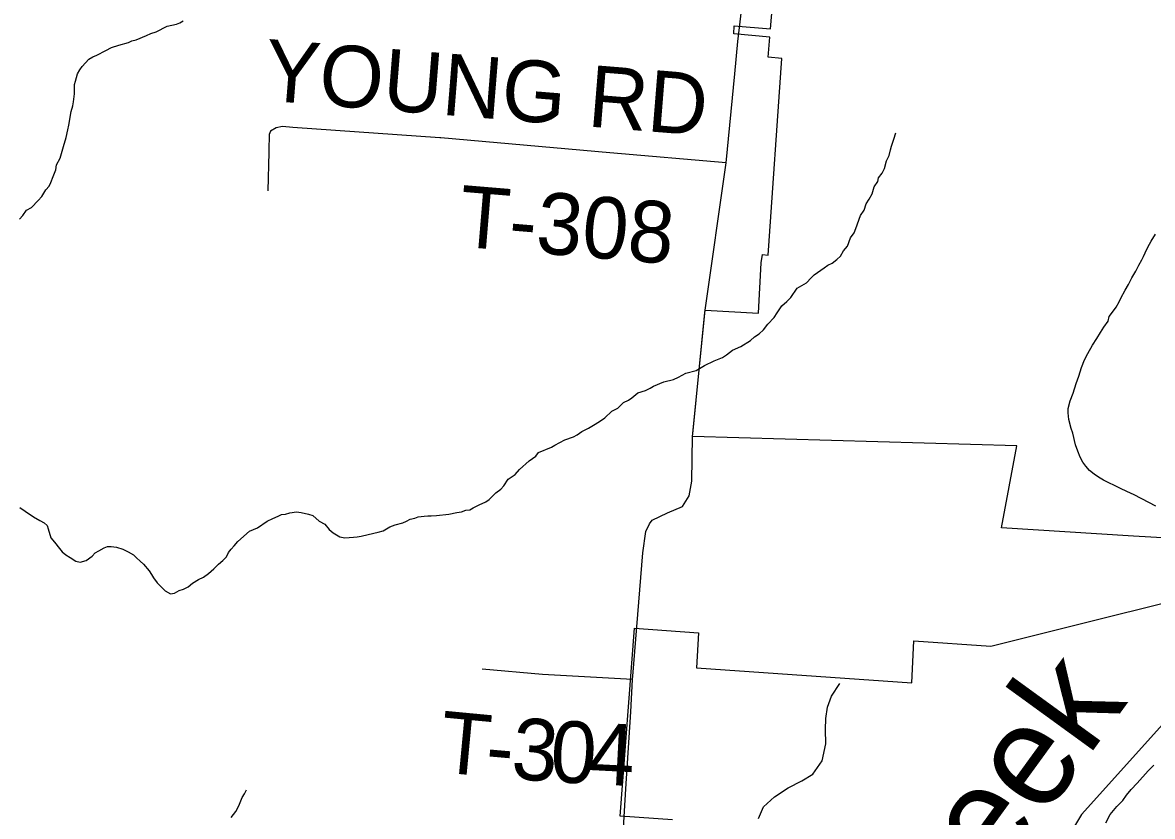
# Model space of a CAD drawing. Extents: x 1310247 to 1664935, y 235267 to 584339.
# Drawn here: x 1473756 to 1479257, y 371649 to 375516 of the extents above; entities that cross this region are included whole.
import ezdxf

# ---------------------------------------------------------------- set-up
doc = ezdxf.new("R2010")
doc.units = 0
for name, color, linetype in [('GM_X_Corporation', 7, 'Continuous'), ('GM_X_Minor_River', 7, 'Continuous'), ('GM_X_Minor_River_Text', 7, 'Continuous'), ('GM_X_Township_Road', 7, 'Continuous'), ('GM_X_Township_Road_Text', 7, 'Continuous')]:
    doc.layers.add(name, color=color, linetype=linetype)

msp = doc.modelspace()

# ---------------------------------------------------------------- linework, layer by layer
at = {"layer": 'GM_X_Corporation'}
for points in [[(1479868, 372973.8), (1479166.1, 373013.9), (1478522.1, 373055.4), (1478596.8, 373453.6), (1477017.5, 373499.2), (1477079.4, 374115.1), (1477339.6, 374100.8), (1477352.5, 374346.2), (1477358.1, 374385.8), (1477386, 374383.3), (1477452.9, 375341.3), (1477386.2, 375347.1), (1477389, 375387), (1477394.1, 375445.4), (1477218.6, 375460.8), (1477221.4, 375500.7), (1477397.6, 375485.3), (1477424.2, 375789.9)], [(1476920.4, 371632.2), (1476666, 371650), (1476735.4, 372566.2), (1477046.7, 372543.4), (1477037.8, 372373.6), (1478085.2, 372300.4), (1478096, 372505.2), (1478471, 372478.9), (1479816.8, 372814.6)], [(1479425.4, 372228.2), (1478912.8, 371658.8), (1478766, 371414.4)]]:
    msp.add_lwpolyline(points, dxfattribs=at)
at = {"layer": 'GM_X_Minor_River'}
for points in [[(1473740.6, 374558.2), (1473757, 374576), (1473775.5, 374601.8), (1473799.8, 374615.4), (1473832.5, 374649), (1473848.9, 374668.8), (1473869.5, 374700.6), (1473885.9, 374718.3), (1473894.2, 374736.3), (1473904.7, 374766.2), (1473917.3, 374798.1), (1473921.7, 374822.2), (1473938.4, 374856), (1473955.4, 374912), (1473968.2, 374955.9), (1473976.8, 374993.9), (1473981.2, 375016), (1473992.4, 375082), (1474000.9, 375110), (1474003.2, 375130.1), (1474007.9, 375168.1), (1474008.6, 375214.3), (1474012.9, 375230.3), (1474023.6, 375266.3), (1474034, 375286.2), (1474046.3, 375302), (1474079, 375337.6), (1474097.2, 375349.4), (1474117.4, 375357), (1474162, 375380.4), (1474188.3, 375394), (1474224.7, 375405.4), (1474271, 375418.6), (1474287.2, 375426.4), (1474309.4, 375432), (1474360, 375453.2), (1474380.2, 375462.9), (1474406.4, 375470.5), (1474459.1, 375497.7), (1474505.4, 375508.9), (1474521.6, 375514.7), (1474537.8, 375524.4)], [(1477036.4, 373821.6), (1477060.7, 373835.3), (1477076.9, 373845), (1477123.5, 373868.3), (1477163.9, 373883.7), (1477184.2, 373897.4), (1477212.7, 373921), (1477253.1, 373938.3), (1477299.8, 373967.7), (1477320.2, 373985.4), (1477342.5, 373999), (1477362.9, 374018.8), (1477385.4, 374046.5), (1477416.1, 374080.1), (1477430.5, 374102), (1477453.2, 374135.7), (1477477.6, 374157.4), (1477496, 374177.1), (1477526.9, 374222.8), (1477573.5, 374248.1), (1477596, 374271.8), (1477610.3, 374287.6), (1477659, 374320.9), (1477677.3, 374334.6), (1477697.6, 374344.3), (1477720, 374362), (1477738.3, 374377.8), (1477752.8, 374403.6), (1477773.2, 374427.4), (1477788, 374467.3), (1477804.4, 374491.1), (1477812.8, 374513), (1477836, 374576.9), (1477854.5, 374602.7), (1477863, 374632.7), (1477877.5, 374656.5), (1477892, 374682.4), (1477902.6, 374716.3), (1477921.1, 374742.1), (1477923.4, 374760.2), (1477941.8, 374781.9), (1477952.3, 374805.9), (1477962.9, 374841.8), (1477975.4, 374867.7), (1477981.9, 374895.7), (1477986.2, 374913.7), (1477998.8, 374947.6), (1478007.4, 374979.6)], [(1479273.5, 373159.8), (1479239.7, 373178.5), (1479168, 373215.9), (1479132.2, 373232.6), (1479102.3, 373247.2), (1479072.4, 373261.8), (1479044.6, 373274.3), (1479018.7, 373286.8), (1478994.8, 373301.3), (1478973, 373315.7), (1478951.2, 373334.2), (1478933.5, 373354.6), (1478917.8, 373374.9), (1478906.1, 373399.2), (1478894.6, 373427.6), (1478883.1, 373459.9), (1478870, 373516.4), (1478862.3, 373538.6), (1478851, 373583), (1478847.6, 373615.2), (1478847.9, 373635.3), (1478856.6, 373673.3), (1478871.2, 373711.2), (1478886.1, 373757.1), (1478898.7, 373793), (1478911.5, 373835), (1478926.2, 373872.9), (1478942.8, 373904.8), (1478965.5, 373944.5), (1478986.1, 373976.3), (1479004.7, 374006.1), (1479021.2, 374031.9), (1479041.8, 374061.7), (1479046.1, 374083.7), (1479058.5, 374099.6), (1479081, 374129.3), (1479095.5, 374155.2), (1479103.9, 374173.1), (1479124.6, 374212.9), (1479141.1, 374240.7), (1479157.7, 374272.6), (1479176.3, 374304.4), (1479190.9, 374334.3), (1479205.4, 374360.1), (1479213.7, 374376), (1479222, 374394), (1479234.5, 374421.9), (1479251.1, 374451.7), (1479271.7, 374485.5)], [(1474344.7, 372878.5), (1474372.2, 372845.9), (1474384, 372827.6), (1474393.7, 372811.4), (1474411.4, 372787), (1474429.1, 372768.5), (1474450.9, 372748.1), (1474476.7, 372733.6), (1474494.9, 372737.3), (1474519.1, 372748.9), (1474539.3, 372756.6), (1474561.6, 372768.2), (1474584, 372785.9), (1474612.4, 372803.5), (1474636.7, 372815.1), (1474661.1, 372832.8), (1474687.5, 372854.4), (1474710, 372878.1), (1474730.4, 372895.8), (1474748.7, 372913.6), (1474759.2, 372935.5), (1474771.5, 372951.4), (1474785.8, 372967.2), (1474804.2, 372989), (1474861.2, 373038.2), (1474899.7, 373055.6), (1474946.4, 373086.9), (1474974.7, 373100.5), (1475001, 373112.1), (1475017.2, 373119.8), (1475035.3, 373121.5), (1475057.5, 373127.1), (1475089.7, 373132.6), (1475111.7, 373130.2), (1475147.7, 373121.5), (1475169.7, 373115.1), (1475199.3, 373086.5), (1475227.2, 373072), (1475248.8, 373047.5), (1475268.6, 373031.1), (1475300.4, 373010.4), (1475324.4, 373006), (1475366.6, 373009.2), (1475384.7, 373011), (1475404.9, 373014.6), (1475439.1, 373022), (1475487.5, 373033.2), (1475511.7, 373040.9), (1475544.1, 373060.4), (1475570.4, 373070), (1475606.7, 373079.4), (1475624.9, 373087.1), (1475643.1, 373096.8), (1475665.3, 373102.5), (1475681.4, 373108.2), (1475711.6, 373111.7), (1475729.7, 373113.4), (1475745.7, 373113.1), (1475771.9, 373114.6), (1475832.2, 373121.6), (1475870.5, 373129), (1475892.6, 373132.6), (1475914.8, 373140.3), (1475932.9, 373142), (1475949.1, 373151.7), (1475979.5, 373167.2), (1476011.9, 373180.7), (1476028.1, 373192.5), (1476060.8, 373226.1), (1476085.2, 373243.7), (1476099.5, 373259.5), (1476120.1, 373291.3), (1476154.6, 373314.8), (1476175.1, 373338.6), (1476222, 373381.9), (1476254.5, 373403.5), (1476268.8, 373421.3), (1476331.5, 373448.3), (1476347.7, 373458.1), (1476396.4, 373483.3), (1476438.8, 373498.7), (1476457, 373508.4), (1476479.3, 373524.1), (1476511.7, 373539.6), (1476544.2, 373559.1), (1476570.6, 373576.7), (1476590.9, 373590.4), (1476625.6, 373623.9), (1476653.9, 373637.5), (1476682.5, 373665.1), (1476706.7, 373676.8), (1476723, 373688.5), (1476751.5, 373712.1), (1476789.8, 373723.5), (1476812.1, 373735.2), (1476828.3, 373744.9), (1476878.9, 373766.1), (1476925.2, 373777.4), (1476949.5, 373789), (1476986, 373808.5), (1477036.4, 373821.6)], [(1473743.1, 373154.2), (1473768.9, 373135.6), (1473808.6, 373108.8), (1473840.4, 373090.2), (1473860.3, 373079.8), (1473876.1, 373065.5), (1473879.8, 373049.3), (1473893.2, 373006.9), (1473910.9, 372984.5), (1473936.4, 372953.9), (1473948.2, 372937.7), (1473966, 372923.3), (1473987.9, 372910.8), (1474015.7, 372892.3), (1474035.7, 372887.9), (1474065.9, 372895.4), (1474094.4, 372917), (1474108.7, 372932.8), (1474127, 372942.6), (1474153.3, 372958.2), (1474169.5, 372963.9), (1474187.5, 372963.6), (1474213.6, 372961.1), (1474243.5, 372950.6), (1474269.4, 372938.1), (1474295.3, 372923.6), (1474311.1, 372909.2), (1474328.9, 372892.8), (1474344.7, 372878.5)], [(1477339.1, 371638.7), (1477364.2, 371696.5), (1477417.2, 371743.8), (1477484.2, 371788.8), (1477551, 371821.8), (1477603.8, 371855), (1477649.1, 371920.4), (1477666.6, 372002.4), (1477665.7, 372072.7), (1477666.7, 372126.9), (1477675.6, 372180.9), (1477694.6, 372234.8), (1477735.8, 372296.3)], [(1479031.2, 371617.3), (1479051.9, 371659.1), (1479084.5, 371696.7), (1479113, 371726.3), (1479131.4, 371752.1), (1479153.9, 371779.9), (1479182.4, 371811.5), (1479237.4, 371870.9), (1479263.9, 371898.5)], [(1474771.5, 371643.8), (1474794.1, 371673.5), (1474808.6, 371701.4), (1474819.1, 371725.3), (1474825.4, 371741.3), (1474835.7, 371759.2), (1474846.1, 371779.1)]]:
    msp.add_lwpolyline(points, dxfattribs=at)
at = {"layer": 'GM_X_Township_Road'}
for points in [[(1477078.3, 374104.2), (1477079.4, 374115.1), (1477181.9, 374832.6), (1477224.2, 375265.9), (1477239.3, 375423.2), (1477279, 375768.6), (1477294.9, 375943.6), (1477361.6, 376587.3)], [(1475791.7, 374954.5), (1475786.9, 374955), (1475071.3, 375004.9), (1475020.9, 375009.7), (1474990.5, 375003.5), (1474963.1, 374986.3), (1474957.3, 374970.9), (1474956.9, 374952.3), (1474955.2, 374911.2)], [(1477181.9, 374832.6), (1476614.7, 374881.2), (1475791.7, 374954.5)], [(1474955.2, 374911.2), (1474954.2, 374884.7), (1474949.3, 374696.6)], [(1477020.5, 373529), (1477078.3, 374104.2)], [(1476726.9, 372332.2), (1476776.8, 372933.2), (1476790.9, 373036.6), (1476808.6, 373073.7), (1476821.9, 373092.5), (1476896.9, 373127.5), (1476969.4, 373159.4), (1477001.2, 373210.6), (1477015.3, 373282.2), (1477017.5, 373499.2), (1477020.5, 373529)], [(1476725.6, 372315.7), (1476288.2, 372340.4), (1475994, 372366.9)], [(1476677.9, 371539.1), (1476693.7, 371783.8), (1476717.6, 372159.3), (1476725.6, 372315.7), (1476726.9, 372332.2)]]:
    msp.add_lwpolyline(points, dxfattribs=at)

# ---------------------------------------------------------------- texts
at = {"layer": 'GM_X_Minor_River_Text'}
msp.add_text('Creek', height=500.11, rotation=54.0084, dxfattribs=at).set_placement((1478090.8, 370762))
at = {"layer": 'GM_X_Township_Road_Text'}
for s, rotation, p in [('YOUNG RD', 355.396, (1474924.7, 375137.3)), ('T-308', 355.2368, (1475871.8, 374425.8)), ('T', 354.605, (1475777.7, 371865.5)), ('3', 355.71, (1476130.1, 371833.1)), ('0', 356.5471, (1476319.2, 371819)), ('4', 357.0657, (1476506.6, 371807.7)), ('-', 354.9878, (1476003.3, 371844.2))]:
    msp.add_text(s, height=300, rotation=rotation, dxfattribs=at).set_placement(p)

doc.saveas('drawing.dxf')
